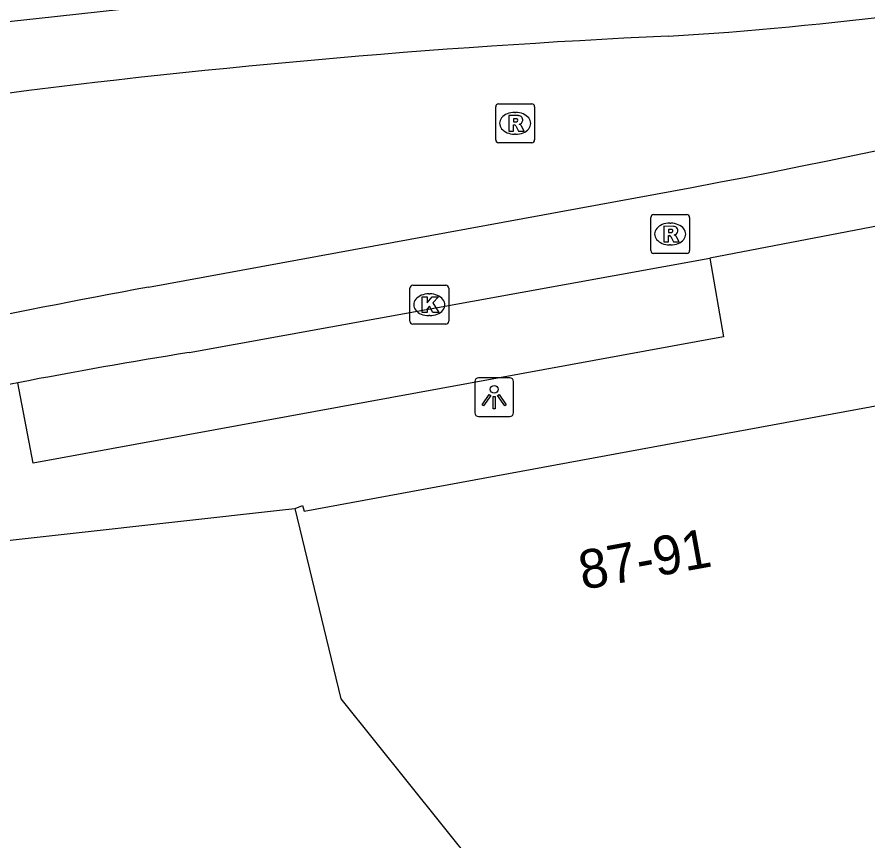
# Model space of a CAD drawing. Extents: x 160664 to 161506, y 382245 to 383288.
# Drawn here: x 161039.18 to 161061.09, y 382914.09 to 382935.28 of the extents above; entities that cross this region are included whole.
import ezdxf

# ---------------------------------------------------------------- set-up
doc = ezdxf.new("R2010")
doc.units = 0
for name, color, linetype in [('IMGEO_Kolk', 7, 'Continuous'), ('IMGEO_Lichtpunt', 7, 'Continuous'), ('IMGEO_Pand', 7, 'Continuous'), ('IMGEO_Pand_nummerreeks', 7, 'Continuous'), ('IMGEO_Rijbaan_lokaal_gesloten', 7, 'Continuous'), ('IMGEO_Rioolput', 7, 'Continuous'), ('IMGEO_Voetpad_open', 7, 'Continuous')]:
    doc.layers.add(name, color=color, linetype=linetype)

msp = doc.modelspace()

# ---------------------------------------------------------------- linework, layer by layer
at = {"layer": 'IMGEO_Kolk'}
for p, q in [((161049.371, 382928.382), (161050.223, 382928.382)), ((161049.296, 382927.456), (161049.296, 382928.308)), ((161049.784, 382928.162), (161049.809, 382928.162)), ((161050.297, 382928.308), (161050.297, 382927.456)), ((161049.807, 382927.602), (161049.782, 382927.602)), ((161050.223, 382927.382), (161049.371, 382927.382))]:
    msp.add_line(p, q, dxfattribs=at)
for points in [[(161049.371, 382928.382), (161050.223, 382928.382)], [(161049.296, 382927.456), (161049.296, 382928.308)], [(161050.297, 382928.308), (161050.297, 382927.456)], [(161049.617, 382928.082), (161049.74, 382928.082), (161049.74, 382927.931), (161049.87, 382928.082), (161050.034, 382928.082), (161049.888, 382927.931), (161050.041, 382927.682), (161049.889, 382927.682), (161049.804, 382927.846), (161049.74, 382927.779), (161049.74, 382927.682), (161049.617, 382927.682), (161049.617, 382928.082)], [(161050.223, 382927.382), (161049.371, 382927.382)]]:
    msp.add_lwpolyline(points, dxfattribs=at)
for centre, start, end in [((161049.373, 382928.306), 91.552, 178.448), ((161049.373, 382928.306), 91.552, 178.448), ((161050.221, 382928.306), 1.552, 88.448), ((161050.221, 382928.306), 1.552, 88.448), ((161049.373, 382927.458), 181.552, 268.448), ((161049.373, 382927.458), 181.552, 268.448), ((161050.221, 382927.458), 271.552, 358.448), ((161050.221, 382927.458), 271.552, 358.448)]:
    msp.add_arc(centre, 0.0765, start, end, dxfattribs=at)
for centre, major_axis, ratio, start_param, end_param in [((161049.783, 382927.882), (-0.387, 0.002), 0.722429, 4.712389, 7.853982), ((161049.808, 382927.882), (-0.39, 0.002), 0.717154, 1.570796, 4.712389)]:
    msp.add_ellipse(centre, major_axis=major_axis, ratio=ratio, start_param=start_param, end_param=end_param, dxfattribs=at)
at = {"layer": 'IMGEO_Lichtpunt'}
for p, q in [((161051.87, 382926.004), (161051.062, 382926.004)), ((161051.87, 382926.004), (161051.062, 382926.004)), ((161050.968, 382925.909), (161050.968, 382925.102)), ((161050.968, 382925.909), (161050.968, 382925.102)), ((161051.964, 382925.102), (161051.964, 382925.909)), ((161051.964, 382925.102), (161051.964, 382925.909)), ((161051.062, 382925.008), (161051.87, 382925.008)), ((161051.062, 382925.008), (161051.87, 382925.008))]:
    msp.add_line(p, q, dxfattribs=at)
for points in [[(161051.342, 382925.573), (161051.381, 382925.545), (161051.193, 382925.283), (161051.155, 382925.31), (161051.342, 382925.573)], [(161051.444, 382925.525), (161051.491, 382925.525), (161051.491, 382925.203), (161051.444, 382925.203), (161051.444, 382925.525)], [(161051.554, 382925.545), (161051.592, 382925.572), (161051.779, 382925.31), (161051.74, 382925.282), (161051.554, 382925.545)]]:
    msp.add_lwpolyline(points, dxfattribs=at)
msp.add_circle((161051.467, 382925.707), 0.0994, dxfattribs=at)
for centre, start, end in [((161051.062, 382925.909), 90, 180), ((161051.062, 382925.909), 90, 180), ((161051.87, 382925.909), 0, 90), ((161051.87, 382925.909), 0, 90), ((161051.062, 382925.102), 180, 270), ((161051.062, 382925.102), 180, 270), ((161051.87, 382925.102), 270, 0), ((161051.87, 382925.102), 270, 360)]:
    msp.add_arc(centre, 0.0946, start, end, dxfattribs=at)
at = {"layer": 'IMGEO_Pand'}
for points in [[(161046.345, 382922.64), (161046.536, 382922.719), (161046.572, 382922.573), (161062.355, 382925.483), (161064.787, 382925.89), (161064.882, 382926.017)], [(161026.456, 382920.431), (161046.091, 382922.612), (161046.345, 382922.64)], [(161057.902, 382904.07), (161051.502, 382912.053), (161051.861, 382912.341), (161047.527, 382917.746), (161046.345, 382922.64)]]:
    msp.add_lwpolyline(points, dxfattribs=at)
at = {"layer": 'IMGEO_Rijbaan_lokaal_gesloten'}
for points in [[(161042.569, 382928.337), (161056.554, 382930.899)], [(161062.834, 382930.198), (161057.022, 382929.08)], [(161043.612, 382926.652), (161057.022, 382929.08)], [(161039.209, 382925.877), (161038.841, 382925.806)]]:
    msp.add_lwpolyline(points, dxfattribs=at)
for centre, radius, start, end in [((161007.021, 383191.848), 265.609, 280.74798, 290.57512), ((161050.326, 383027.378), 92.757, 273.47322, 288.93319), ((161077.257, 382597.76), 339.566, 93.73679, 96.72873), ((161065.688, 382722.808), 212.208, 92.63145, 97.55421), ((161077.931, 382735.933), 195.626, 100.4143, 106.89826), ((161065.921, 382787.01), 141.412, 99.07701, 100.88847)]:
    msp.add_arc(centre, radius, start, end, dxfattribs=at)
at = {"layer": 'IMGEO_Rioolput'}
for p, q in [((161051.506, 382932.124), (161051.506, 382932.976)), ((161051.581, 382933.05), (161052.433, 382933.05)), ((161052.507, 382932.976), (161052.507, 382932.124)), ((161051.994, 382932.83), (161052.019, 382932.83)), ((161052.017, 382932.27), (161051.992, 382932.27)), ((161052.433, 382932.05), (161051.581, 382932.05)), ((161055.497, 382929.275), (161055.497, 382930.127)), ((161055.572, 382930.201), (161056.424, 382930.201)), ((161056.498, 382930.127), (161056.498, 382929.275)), ((161055.985, 382929.981), (161056.01, 382929.981)), ((161056.008, 382929.421), (161055.983, 382929.421)), ((161056.424, 382929.201), (161055.572, 382929.201))]:
    msp.add_line(p, q, dxfattribs=at)
for points in [[(161051.506, 382932.124), (161051.506, 382932.976)], [(161051.581, 382933.05), (161052.433, 382933.05)], [(161052.507, 382932.976), (161052.507, 382932.124)], [(161052.095, 382932.748), (161051.843, 382932.75), (161051.843, 382932.35)], [(161052.021, 382932.669), (161051.967, 382932.669), (161051.967, 382932.588)], [(161051.967, 382932.588), (161052.019, 382932.588)], [(161051.843, 382932.35), (161051.967, 382932.35), (161051.967, 382932.512), (161051.978, 382932.512)], [(161052.025, 382932.483), (161052.096, 382932.35), (161052.236, 382932.35), (161052.171, 382932.476)], [(161052.433, 382932.05), (161051.581, 382932.05)], [(161055.497, 382929.275), (161055.497, 382930.127)], [(161055.572, 382930.201), (161056.424, 382930.201)], [(161056.498, 382930.127), (161056.498, 382929.275)], [(161056.086, 382929.899), (161055.834, 382929.901), (161055.834, 382929.501)], [(161056.012, 382929.82), (161055.958, 382929.82), (161055.958, 382929.739)], [(161055.958, 382929.739), (161056.01, 382929.739)], [(161055.834, 382929.501), (161055.958, 382929.501), (161055.958, 382929.663), (161055.969, 382929.663)], [(161056.016, 382929.634), (161056.087, 382929.501), (161056.227, 382929.501), (161056.162, 382929.627)], [(161056.424, 382929.201), (161055.572, 382929.201)]]:
    msp.add_lwpolyline(points, dxfattribs=at)
for centre, radius, start, end in [((161051.583, 382932.974), 0.0765, 91.552, 178.448), ((161051.583, 382932.974), 0.0765, 91.552, 178.448), ((161052.431, 382932.974), 0.0765, 1.552, 88.448), ((161052.431, 382932.974), 0.0765, 1.552, 88.448), ((161052.094, 382932.638), 0.109, 350.3612, 89.416), ((161052.003, 382932.777), 0.19, 274.7715, 282.9687), ((161052.027, 382932.573), 0.0964, 77.0061, 93.1865), ((161052.041, 382932.63), 0.0378, 276.6634, 79.6772), ((161052.092, 382932.638), 0.112, 277.5842, 350.9817), ((161052.076, 382932.423), 0.108, 29.5134, 73.7905), ((161051.977, 382932.459), 0.0533, 26.0293, 88.6989), ((161051.583, 382932.126), 0.0765, 181.552, 268.448), ((161051.583, 382932.126), 0.0765, 181.552, 268.448), ((161052.431, 382932.126), 0.0765, 271.552, 358.448), ((161052.431, 382932.126), 0.0765, 271.552, 358.448), ((161055.574, 382930.125), 0.0765, 91.552, 178.448), ((161055.574, 382930.125), 0.0765, 91.552, 178.448), ((161056.422, 382930.125), 0.0765, 1.552, 88.448), ((161056.422, 382930.125), 0.0765, 1.552, 88.448), ((161056.085, 382929.789), 0.109, 350.3612, 89.416), ((161055.994, 382929.928), 0.19, 274.7715, 282.9687), ((161056.018, 382929.724), 0.0964, 77.0061, 93.1865), ((161056.032, 382929.781), 0.0378, 276.6634, 79.6772), ((161056.083, 382929.789), 0.112, 277.5842, 350.9817), ((161056.067, 382929.574), 0.108, 29.5134, 73.7905), ((161055.968, 382929.61), 0.0533, 26.0293, 88.6989), ((161055.574, 382929.277), 0.0765, 181.552, 268.448), ((161055.574, 382929.277), 0.0765, 181.552, 268.448), ((161056.422, 382929.277), 0.0765, 271.552, 358.448), ((161056.422, 382929.277), 0.0765, 271.552, 358.448)]:
    msp.add_arc(centre, radius, start, end, dxfattribs=at)
for centre, major_axis, ratio, start_param, end_param in [((161051.993, 382932.55), (-0.387, 0.002), 0.722429, 4.712389, 7.853982), ((161052.018, 382932.55), (-0.39, 0.002), 0.717154, 1.570796, 4.712389), ((161055.984, 382929.701), (-0.387, 0.002), 0.722429, 4.712389, 7.853982), ((161056.009, 382929.701), (-0.39, 0.002), 0.717154, 1.570796, 4.712389)]:
    msp.add_ellipse(centre, major_axis=major_axis, ratio=ratio, start_param=start_param, end_param=end_param, dxfattribs=at)
at = {"layer": 'IMGEO_Voetpad_open'}
msp.add_lwpolyline([(161057.022, 382929.08), (161057.369, 382927.06), (161039.6, 382923.81), (161039.209, 382925.877)], dxfattribs=at)

# ---------------------------------------------------------------- texts
at = {"layer": 'IMGEO_Pand_nummerreeks'}
msp.add_text('87-91', height=1, rotation=10.319, dxfattribs=at).set_placement((161053.745, 382920.545))

doc.saveas('drawing.dxf')
